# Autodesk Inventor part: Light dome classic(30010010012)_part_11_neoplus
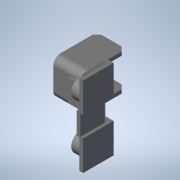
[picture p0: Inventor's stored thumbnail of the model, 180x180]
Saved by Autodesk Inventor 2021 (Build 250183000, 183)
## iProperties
Created: 2026-04
Part Number: Light dome classic(30010010012)_part_11_neoplus
Material: Generic
Catalog Web Link: www.3dfindit.com
Description: Light dome classic_part_11_neoplus-
Vendor: KINGSPAN
Document SubType Name: Modeling
Designer: psAdmin
Manufacturer: KINGSPAN
Mass: 10.2531 g
Surface Area: 82.6879 cm^2
Volume: 10.2531 cm^3
Density: 1 g/cm^3
Appearance: PSOLRGB-255-255-255
Category: PARTsolutions
Company: KINGSPAN
Title: Light dome classic(30010010012)_part_11_neoplus
Author: Cadenas PARTsolutions
PSOL_IDENT_0: {$CADENAS_DATA/23d-libs/kingspan_kla/light_dome_classic_neoplus/parts/part_11.prj},281 {VTYP=3D},{NB=
PSOL_IDENT_1: Light dome classic(30010010012)_part_11_neoplus},{LINA=Light dome classic(30010010012)_part_11_neopl
PSOL_IDENT_2: us},{NN=Light dome classic_part_11_neoplus},{DATE=15.07.2024 10:56:16},{GEOMDATE=01.07.2024 06:37:04
PSOL_IDENT_3: },{VERSION=},{LINEID=10},{WBVAR=LODLEVEL,L,W,DP,OP},{WBNUMERIC=W}  {NB=Light dome classic(3001001001
PSOL_IDENT_4: 2)_part_11_neoplus},{LINA=Light dome classic(30010010012)_part_11_neoplus},{KT=DUMMY},{IDNR=},{PN=Li
PSOL_IDENT_5: ght dome classic},{LODLEVEL=300},{L=100},{W=100},{DRIVE=1},{WX=100,150,200,250,300},{DP=1},{OP=2},{O
PSOL_IDENT_6: PX='1','manualy','2','Linear drive 300 mm stroke 24 V and 230 V','3','Linear drive 500 mm stroke 24
PSOL_IDENT_7: V and 230 V'},{LX=1000},{XWX=1000},{VER=1},{DPX='3', 'Fixed','1', 'Natural ventilation' ,'4','NSHE',
PSOL_IDENT_8: '2', 'NSHEV'}
NB: Light dome classic(30010010012)_part_11_neoplus
NN: Light dome classic_part_11_neoplus
NBSYN: $PN.($LODLEVEL.$L.$W.$DP.$OP.)_part_11_neoplus
LINA: Light dome classic(30010010012)_part_11_neoplus
CATALOG: Light + Air
PN: Light dome classic
LODLEVEL: 300
L: 100
W: 100
DP: Natural ventilation
OP: Linear drive 300 mm stroke 24 V and 230 V
SUPPLIER: KINGSPAN
ARTICLENO: Light dome classic(30010010012)_part_11_neoplus
BOMINFO: Light dome classic(30010010012)_part_11_neoplus
CREATOR: CADENAS GmbH
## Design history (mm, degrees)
sketch "Sketch_1"
  geometry: L1 (-12, 32)-(-34.5, 32); L2 (-34.5, 32)-(-34.5, 48.5); L3 (-34.5, 48.5)-(-37, 48.5); L4 (-37, 48.5)-(-37, 32.5); L5 (-34, 29.5)-(-12, 29.5); L6 (-12, 29.5)-(-12, 32); A1 r 3 centre (-34, 32.5) between (-37, 32.5) and (-34, 29.5)
  constraints: 12 end point, 2 point on circle, 1 centre point
extrude "Extrusion1" join sketch "Sketch_1" stored distance "d0" = 15.02; taper "d1" = 0 deg
sketch "Sketch_2"
  geometry: L1 (12, -30)-(36.5, -30); L2 (36.5, -30)-(36.5, -48.5); L3 (36.5, -48.5)-(39, -48.5); L4 (39, -48.5)-(39, -27.5); L5 (39, -27.5)-(12, -27.5); L6 (12, -27.5)-(12, -30)
  constraints: 12 end point
extrude "Extrusion2" join sketch "Sketch_2" distance "d2" = 20.49; taper "d3" = 0 deg
sketch "Sketch_3"
  geometry: L1 (12, -30)-(36.5, -30); L2 (36.5, -30)-(36.5, -48.5); L3 (36.5, -48.5)-(39, -48.5); L4 (39, -48.5)-(39, -27.5); L5 (39, -27.5)-(12, -27.5); L6 (12, -27.5)-(12, -30)
  constraints: 12 end point
extrude "Extrusion3" join sketch "Sketch_3" distance "d4" = 20.49; taper "d5" = 0 deg
sketch "Sketch_4"
  geometry: L1 (-20, 27.5)-(-20, -27.5); L2 (-20, -27.5)-(34, -27.5); L3 (34, -27.5)-(20, -12.5); L4 (20, -12.5)-(20, -7.51); L5 (20, -7.51)-(0, -7.51); L6 (0, -7.51)-(0, 7.51); L7 (0, 7.51)-(20, 7.51); L8 (20, 7.51)-(20, 12.5); L9 (20, 12.5)-(34, 27.5); L10 (34, 27.5)-(-20, 27.5)
  constraints: 20 end point
extrude "Extrusion4" cut sketch "Sketch_4" distance "d6" = 50; taper "d7" = 0 deg
sketch "Sketch_5"
  geometry: L1 (-12.5, 25)-(-12.5, 0); L2 (-12.5, 0)-(-10, 0); L3 (-10, 0)-(-10, 25); L4 (-7.5, 27.5)-(7.5, 27.5); L5 (10, 25)-(10, 0); L6 (10, 0)-(12.5, 0); L7 (12.5, 0)-(12.5, 25); L8 (7.5, 30)-(-7.5, 30); A1 r 5 centre (-7.5, 25) between (-7.5, 30) and (-12.5, 25); A2 r 2.5 centre (-7.5, 25) between (-7.5, 27.5) and (-10, 25); A3 r 2.5 centre (7.5, 25) between (10, 25) and (7.5, 27.5); A4 r 5 centre (7.5, 25) between (12.5, 25) and (7.5, 30)
  constraints: 16 end point, 8 point on circle, 4 centre point
extrude "Extrusion5" join sketch "Sketch_5" distance "d8" = 20; taper "d9" = 0 deg
sketch "Sketch_6"
  geometry: L1 (5, 20)-(0, 20); L2 (0, 20)-(0, 3); L3 (0, 3)-(-3, 0); L4 (-3, 0)-(-17, 0); L5 (-17, 0)-(-20, 3); L6 (-20, 3)-(-20, 20); L7 (-20, 20)-(-25, 20); L8 (-25, 20)-(-25, -5); L9 (-25, -5)-(5, -5); L10 (5, -5)-(5, 20)
  constraints: 20 end point
extrude "Extrusion6" cut sketch "Sketch_6" stored distance "d10" = 60; taper "d11" = 0 deg
sketch "Sketch_10"
  geometry: L1 (30.6, -41.5)-(36.5, -41.5); L2 (36.5, -41.5)-(36.5, -48.25); L3 (36.5, -48.25)-(30.6, -48.25); L4 (30.6, -48.25)-(30.6, -41.5); L5 (30.6, -41.5)-(36.5, -41.5)
  constraints: 10 end point
revolve "Revolution1" sketch "Sketch_10" stored, may be unused: angle "d12" = 360 deg
sketch "Sketch_11"
  geometry: L1 (30.6, -41.5)-(36.5, -41.5); L2 (36.5, -41.5)-(36.5, -48.25); L3 (36.5, -48.25)-(30.6, -48.25); L4 (30.6, -48.25)-(30.6, -41.5); L5 (30.6, -41.5)-(36.5, -41.5)
  constraints: 10 end point
revolve "Revolution2" sketch "Sketch_11" stored, may be unused: angle "d13" = 360 deg
node "IP_11_XY"
node "IP_11_YZ"
node "IP_11_ZX"
node "IP_11_X"
node "IP_11_Y"
node "IP_11_Z"
node "IP_11_Center"
body "Solid1"
